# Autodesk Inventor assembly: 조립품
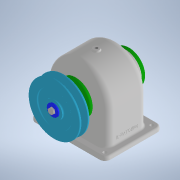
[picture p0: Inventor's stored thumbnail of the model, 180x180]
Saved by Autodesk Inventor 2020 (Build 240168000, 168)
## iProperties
Created: 2022-09
Part Number: 조립품
Document SubType Name: Assembly
Designer: Administrator
Author: Administrator
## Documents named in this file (16)
- C:\Users\Administrator\Desktop\720906V1018\답안조립품.iam
- C:\Users\Administrator\Desktop\720906V1018\본체.ipt
- C:\Users\Administrator\Desktop\720906V1018\축.ipt
- C:\Users\Administrator\Desktop\720906V1018\키 6 x 6 x 22.ipt
- C:\Users\Administrator\Desktop\720906V1018\뒤커버.ipt
- C:\Users\Administrator\Desktop\720906V1018\앞커버.ipt
- C:\Users\Administrator\Desktop\720906V1018\볼트 M3 x 10.ipt
- C:\Users\Administrator\Desktop\720906V1018\키 5 x 5 x 18.ipt
- C:\Users\Administrator\Desktop\720906V1018\V-벨트풀리.ipt
- C:\Users\Administrator\Desktop\720906V1018\멈춤나사 M4 x 10.ipt
- C:\Users\Administrator\Desktop\720906V1018\와셔 6 x 22.ipt
- C:\Users\Administrator\Desktop\720906V1018\육각머리볼트 M3 x 8.ipt
- C:\Users\Administrator\Desktop\720906V1018\베어링 6203.ipt
- C:\Users\Administrator\Desktop\720906V1018\칼라.ipt
- C:\Users\Administrator\Desktop\720906V1018\오일 실 17 x 30 x 8.ipt
- C:\Users\Administrator\Desktop\720906V1018\스퍼기어.ipt
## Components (9 placed, 2 different names)
1. V-벨트풀리:1 — 플러쉬:1
2. ISO 4762 M3 x 10:2
3. ISO 4762 M3 x 10:3
4. ISO 4762 M3 x 10:4
5. ISO 4762 M3 x 10:5
6. ISO 4762 M3 x 10:1
7. ISO 4762 M3 x 10:6
8. ISO 4762 M3 x 10:7
9. ISO 4762 M3 x 10:8
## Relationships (1: Flush 1)
- 플러쉬:1 [Flush]: V-벨트풀리:1
